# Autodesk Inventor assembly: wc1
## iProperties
Shininess: 64.0
Length Units: 11272
Angle Units: 11279
Time Units: 11290
Mass Units: 11286
Length Display Precision: 3
Angle Display Precision: 2
Compacted: True
Part Number: wc1
Document SubType Name: Assembly
Created: 2004-08
Designer: John Blackburn
Manufacturer: Standard
Standards Organization: Custom
Density: 0.0
Volumn: 0.0
Area: 0.0
PropertySet Name: Model Information
Control State: 0
Master: False
Checked Out: False
Author: John Blackburn
